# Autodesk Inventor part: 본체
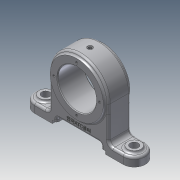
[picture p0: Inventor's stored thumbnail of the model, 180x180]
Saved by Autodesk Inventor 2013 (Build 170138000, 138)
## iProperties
Created: 2019-05
Part Number: 본체
Material: 알루미늄 6061
Document SubType Name: Modeling
Designer: user
Density: 2.71 g/cm^3
Mass: 457.703 g
Surface Area: 318.8 cm^2
Volume: 168.894 cm^3
Author: user
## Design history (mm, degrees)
sketch "스케치1"
  geometry: C1 r 26 at (0, 0); C2 r 36 at (0, 0); 1 further point
  constraints: 2 centre point, 2 coincident
  dimensions: "d0" = 52 diameter of C1; "d3" = 72 diameter of C2
extrude "돌출1" new body sketch "스케치1" stored distance "d4" = 36; taper "d5" = 0 deg
node "작업 평면1"
sketch "스케치2"
  geometry: C1 r 40 at (0, 0); C2 r 36 at (0, 0); 1 further point
  constraints: 2 centre point, 2 coincident
  dimensions: "d6" = 80 diameter of C1; "d9" = 72 diameter of C2
extrude "돌출2" join sketch "스케치2" stored distance "d10" = 30; taper "d11" = 0 deg
fillet "모깎기1" dims "d12" = 3
sketch "스케치3" dims "d13" = 62
  geometry: L1 (0, 0)-(0, 31); C1 r 36 at (0, 0) reference; 1 further point
  constraints: 2 coincident, 2 end point, 1 vertical, 1 vertical alignment, 2 other
hole "구멍1" sketch "스케치3" at (0, 31) diameter "d15" = 3.242; stored, may be unused: countersink angle "d19" = 90 deg, drill point angle "d21" = 118 deg; dims "d16" = 6, "d17" = 4, "d18" = 2, "d20" = 8
node "작업 평면2"
node "작업 평면3"
node "작업 평면4"
sketch "스케치6"
  geometry: L1 (40, 0)-(40, -48); L2 (40, -48)-(75, -48); L3 (75, -48)-(75, -60); L4 (75, -60)-(36, -60); L5 (36, -60)-(36, -56); L6 (36, -56)-(30, -56); L7 (30, -56)-(30, -50); L8 (30, -50)-(0, -50); L9 (0, -50)-(0, 5.081); L10 (-40, 0)-(-40, -48); L11 (-40, -48)-(-75, -48); L12 (-75, -48)-(-75, -60); L13 (-75, -60)-(-36, -60); L14 (-36, -60)-(-36, -56); L15 (-36, -56)-(-30, -56); L16 (-30, -56)-(-30, -50); L17 (-30, -50)-(0, -50); C1 r 26 at (0, 0) reference; A1 r 40 centre (0, 0) between (-40, 0) and (40, 0); 2 further points
  constraints: 34 end point, 8 symmetric about line, 7 parallel, 2 point on circle, 2 vertical, 1 centre point, 1 coincident, 1 horizontal alignment, 1 perpendicular, 1 point on line, 1 other
  dimensions: "d39" = 100 dimension on L4; "d40" = 10 distance between parallel lines of L8 L4; "d41" = 60 diameter of L7 L9; "d43" = 72 diameter of L5 L9; "d44" = 12 distance of L2.end L3.end; "d45" = 4 distance of L4.end L5.end; "d46" = 150 diameter of L3 L9
extrude "돌출4" join sketch "스케치6" stored distance "d47" = 30; taper "d48" = 0 deg
sketch "스케치7"
  geometry: L1 (0, 0)-(0, 30) reference; L2 (0, 30)-(35, 30) reference; L3 (150, 0)-(150, 30) reference; L4 (115, 30)-(150, 30) reference; C1 r 9 at (15, 15); C2 r 9 at (135, 15); 1 further point
  constraints: 2 centre point, 1 equal radius
  dimensions: "d49" = 18 diameter of C1; "d51" = 15 distance from line of L2 C1.centre; "d53" = 15 distance from line of L4 C2.centre; "d54" = 120 distance of C1.centre C2.centre; "d55" = 15 distance from line of C1.centre L1
extrude "돌출5" join sketch "스케치7" distance "d56" = 3; taper "d57" = 0 deg
fillet "모깎기2" dims "d58" = 3
sketch "스케치8"
  geometry: C1 r 9 at (0, 0) reference; C2 r 5.5 at (0, 0); C3 r 9 at (120, 0) reference; C4 r 5.5 at (120, 0); 1 further point
  constraints: 2 centre point, 2 coincident
  dimensions: "d59" = 11 diameter of C2; "d61" = 11 diameter of C4
extrude "돌출6" cut sketch "스케치8" stored distance "d62" = 3; taper "d63" = 0 deg
chamfer "모따기1" distance "d64" = 1; stored, may be unused: second distance "d65" = 2, angle "d66" = 45 deg
fillet "모깎기3" dims "d67" = 15
fillet "모깎기4" dims "d68" = 6
fillet "모깎기5" dims "d69" = 3
fillet "모깎기6" dims "d70" = 3
fillet "모깎기7" dims "d71" = 3
sketch "스케치9"
  geometry: L1 (-27, -50)-(27, -50) reference; L2 (0, 0)-(0, -61.39); A1 r 39 centre (0, 0) between (-37, -12.329) and (37, -12.329) reference; 1 further point
  constraints: 2 end point, 1 perpendicular, 1 point on line, 1 other
  dimensions: "d72" = 7 distance from line of L1 point (0, -43)
extrude "돌출7" join sketch "스케치9" distance "d73" = 0.5; taper "d74" = 0 deg
sketch "스케치10"
  geometry: C1 r 1.5 at (0, 26); 1 further point
  constraints: 1 centre point, 1 vertical alignment, 1 other
  dimensions: "d77" = 3 diameter of C1
extrude "돌출8" cut sketch "스케치10" stored distance "d79" = 12; taper "d80" = 0 deg
node "작업 평면5"
sketch "스케치11"
  geometry: 1 further point
hole "구멍3" sketch "스케치11" at (0, 0) diameter "d81" = 4.917; stored, may be unused: countersink angle "d85" = 90 deg, drill point angle "d87" = 118 deg; dims "d82" = 7, "d83" = 7, "d84" = 1, "d86" = 9
sketch "스케치12"
  geometry: C1 r 1 at (0, 0); 1 further point
  constraints: 1 centre point, 1 coincident
  dimensions: "d88" = 2 diameter of C1
extrude "돌출9" cut sketch "스케치12" stored distance "d90" = 12; taper "d91" = 0 deg
node "솔리드1"
pattern_circular "원형 패턴1" dims angle "d23" = 360 deg
mirror "대칭1"
node "투영된 루프1"
